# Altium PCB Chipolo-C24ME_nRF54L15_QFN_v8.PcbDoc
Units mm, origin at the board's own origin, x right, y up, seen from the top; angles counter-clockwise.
Board outline 27.05 x 32.39 mm, 2 copper layers (Top Layer, Bottom Layer), stack 0.58 mm thick; 46 components, 34 nets, 183 pads, 310 vias.
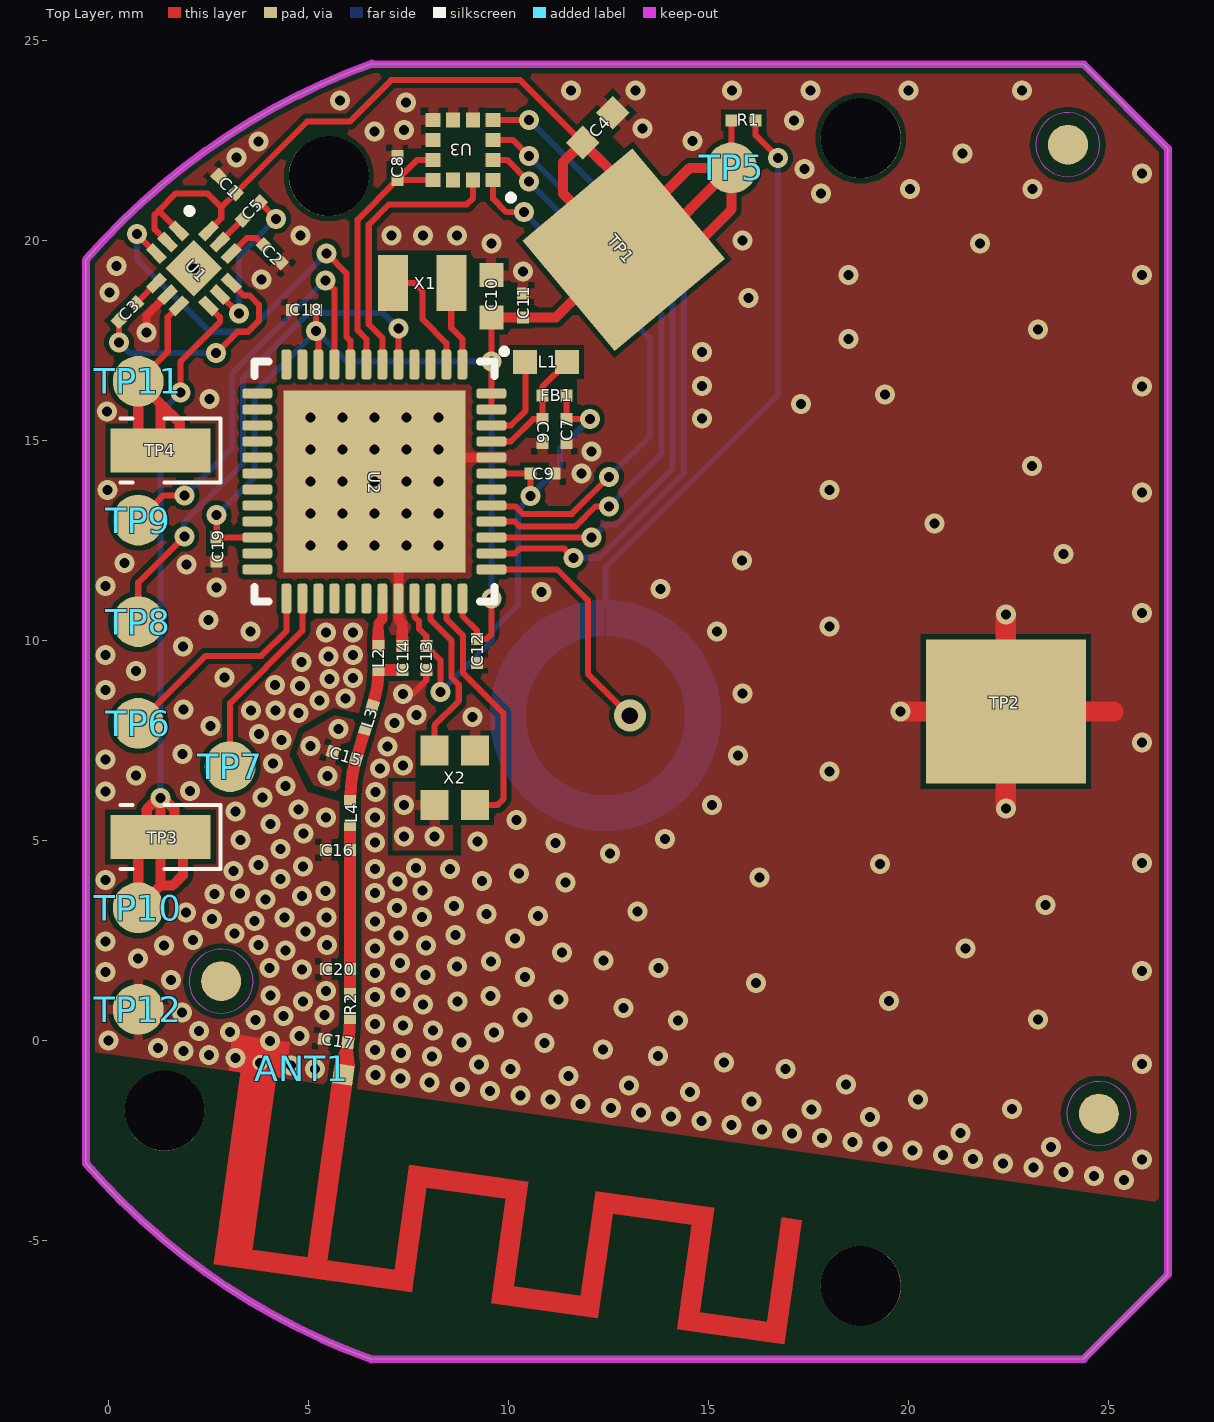
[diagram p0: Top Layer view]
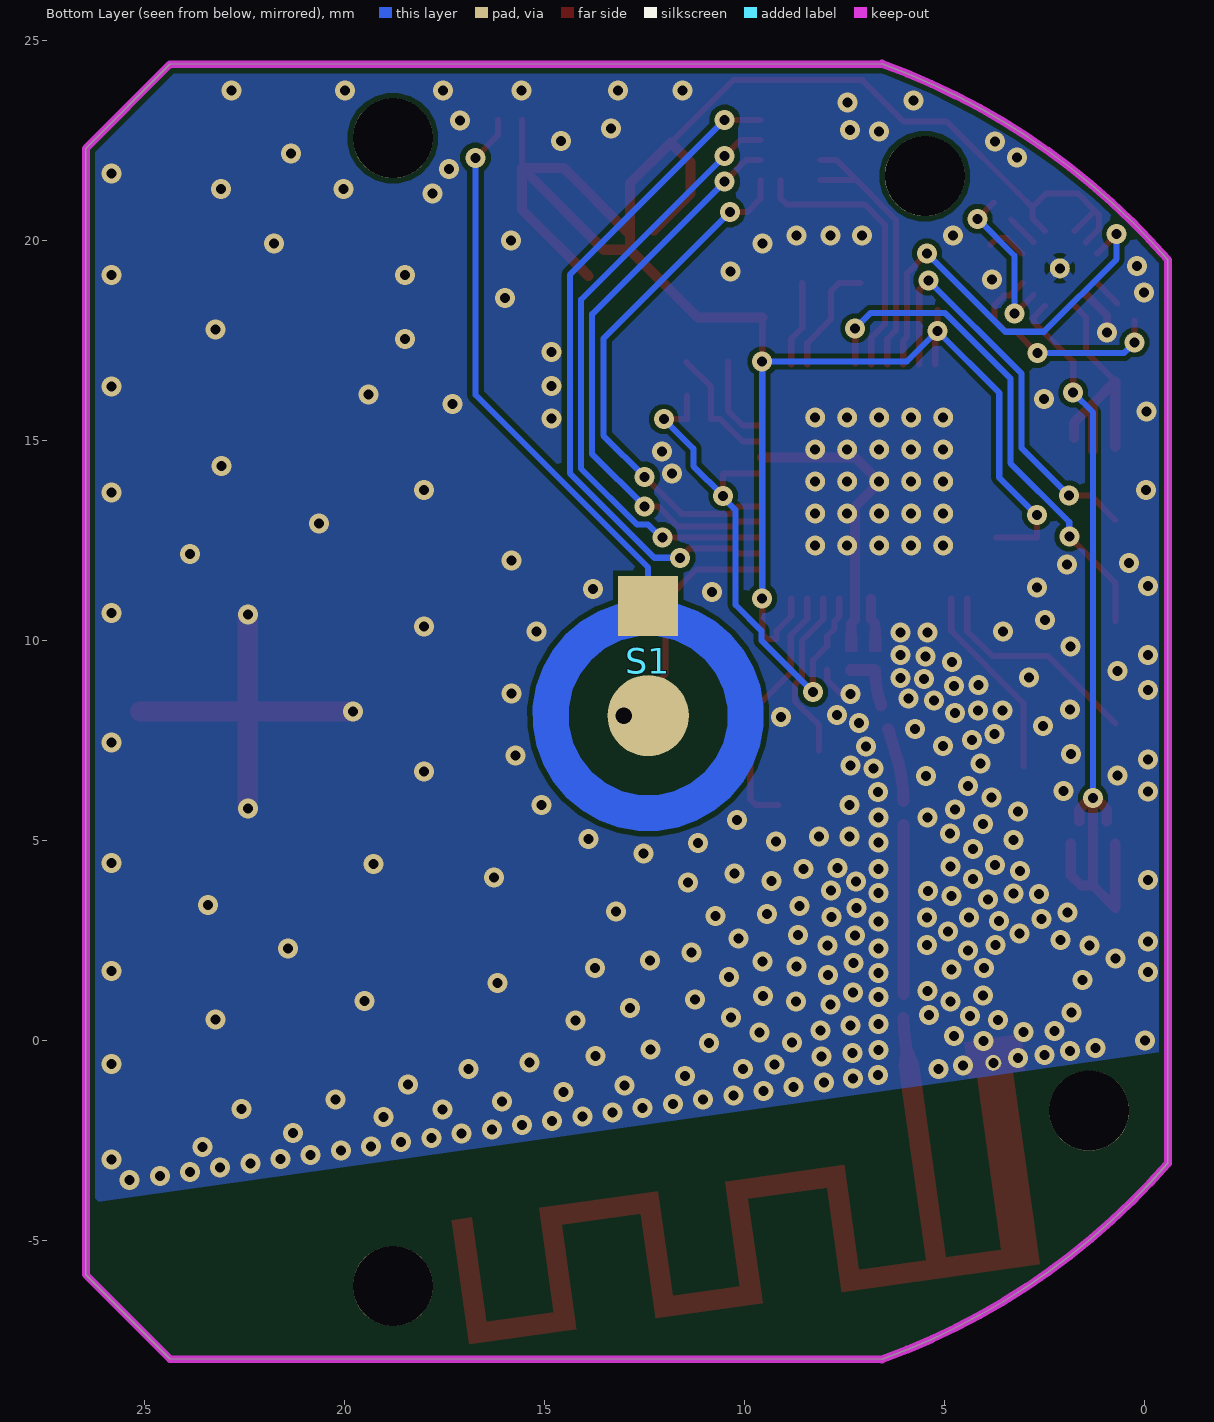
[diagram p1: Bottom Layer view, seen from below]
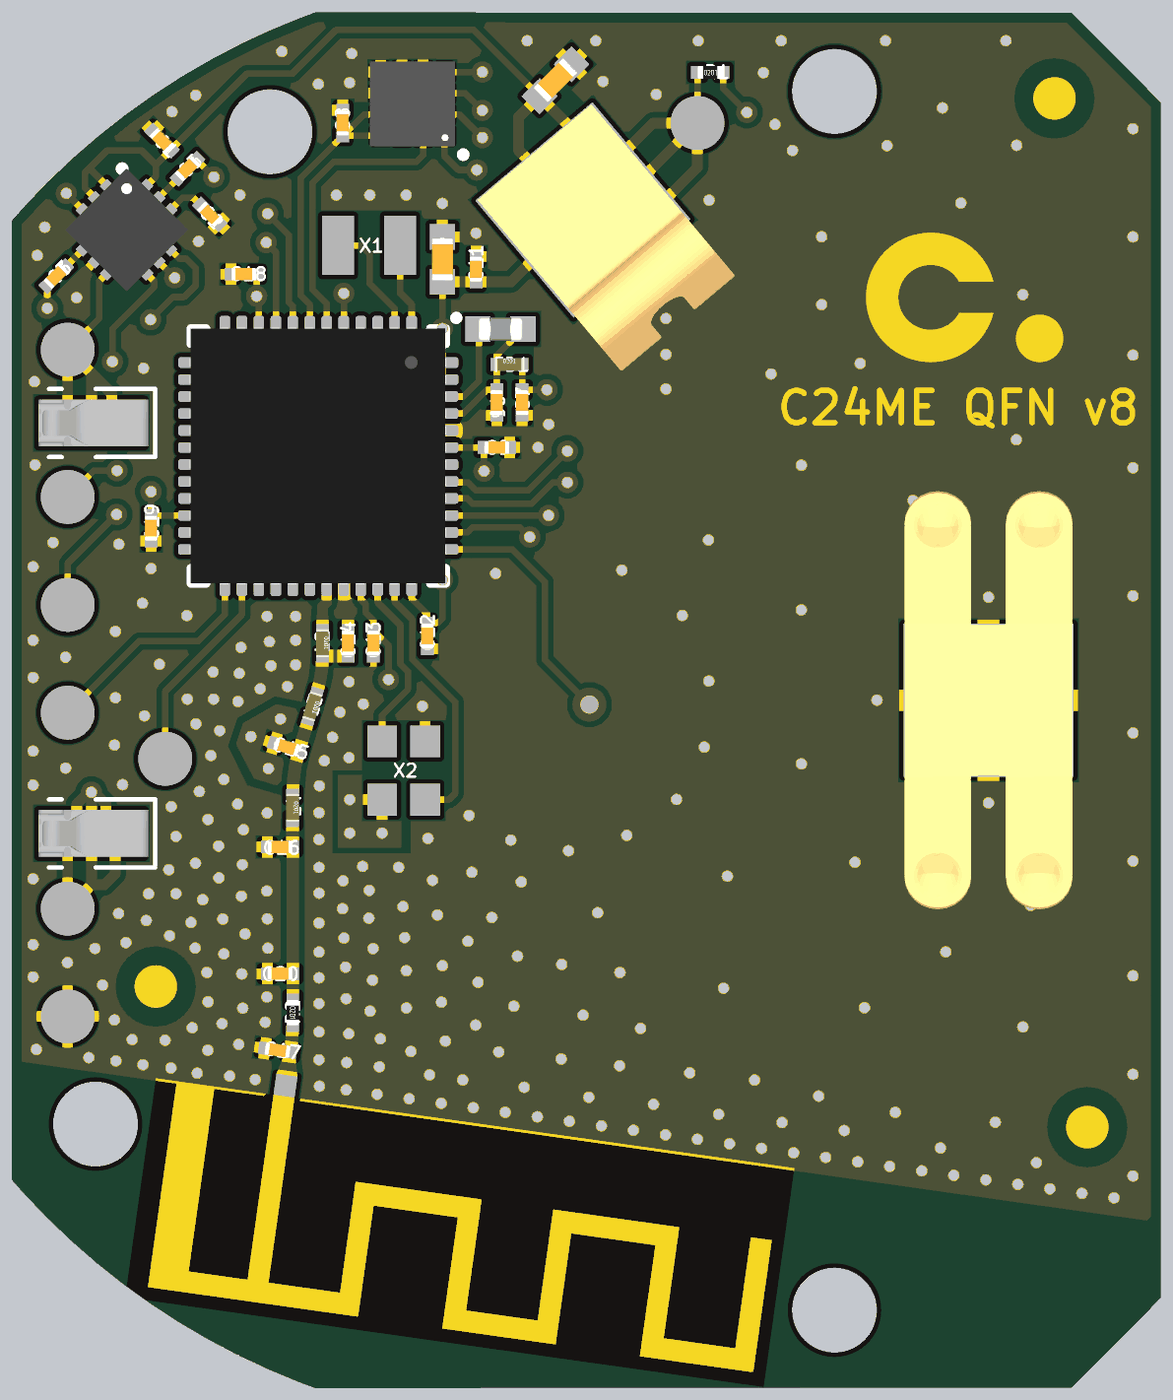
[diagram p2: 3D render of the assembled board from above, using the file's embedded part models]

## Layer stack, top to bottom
Top Solder: solder mask 0.0102, Solder Resist, Dk 3.5
Top Layer: signal copper 0.0356
Dielectric 1: dielectric 0.5086, FR-4, Dk 4.8
Bottom Layer: signal copper 0.0356
Bottom Solder: solder mask 0.0102, Solder Resist, Dk 3.5

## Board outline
-0.574,-3.072 -0.574,19.514 cw(c12.434,8.208) 5.235,23.867 5.233,23.868 cw(c12.426,8.221) 6.573,24.416 24.377,24.403 26.477,22.301 26.477,-5.858 24.377,-7.96 6.573,-7.974 cw(c12.425,8.22)

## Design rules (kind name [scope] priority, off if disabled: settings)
Clearance [All] p1: gap=0.127 ignorepadtopadclearanceinfootprint=FALSE except(0: Arc-Hole Track-Hole SMDPad-Hole THPad-Hole Via-Hole Fill-Hole Poly-Hole Region-Hole Text-Hole)
Clearance Clearance_Polygon [InPolygon] p2: gap=0.127 ignorepadtopadclearanceinfootprint=FALSE
HoleToHoleClearance [All] p1: gap=0.127 allowstackedmicrovias=TRUE
MinimumSolderMaskSliver [All] p1: minsoldermaskwidth=0
PolygonConnect PolygonConnect-ThermalPad [InComponent('U2') AND InNet('GND')] p1: connectstyle=Direct reliefconductorwidth=0.254 reliefentries=4 polygonreliefangle="90 Angle" airgapwidth=0.254
PolygonConnect PolygonConnect_Vias [IsVia] p2: connectstyle=Direct reliefconductorwidth=0.254 reliefentries=4 polygonreliefangle="90 Angle" airgapwidth=0.254
PolygonConnect PolygonConnect_Antenna [(InComponent('ANT1') AND InNet('GND'))] p3: connectstyle=Direct reliefconductorwidth=0.254 reliefentries=4 polygonreliefangle="90 Angle" airgapwidth=0.254
PolygonConnect PolygonConnect_Pads [(InPadClass('All Pads'))] p4: connectstyle=Relief reliefconductorwidth=0.254 reliefentries=4 polygonreliefangle="90 Angle" airgapwidth=0.127
RoutingVias [All] p1: holewidth=0.25 width=0.5 viastyle="Through Hole" minholewidth=0.25 minwidth=0.25 maxholewidth=0.5 maxwidth=1
ShortCircuit ShortCircuit_Antenna [InComponent('ANT1')] p1: allowed=TRUE
ShortCircuit [All] p2: allowed=FALSE
SilkToSilkClearance [All] p1: silktosilkclearance=0.152
SilkToSolderMaskClearance [IsPad] p1: minsilkscreentomaskgap=0.15 clearancetoexposedcopper=TRUE
SolderMaskExpansion SolderMaskExpansion_U1 [InComponent('U1')] p1: expansion=0.048 istentingtop=FALSE
SolderMaskExpansion [All] p2: expansion=0.102 istentingtop=FALSE
Width [All] p1: maxlimit=0.762 minlimit=0.127 preferedwidth=0.152 minimp=50.000000 maximp=50.000000 favimp=50.000000
25 further rules are at their usual default settings.

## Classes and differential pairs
net class C20_Nets: GND NetC16_1
net class FB1_Nets: DECA DECD
net class C9_Nets: DECA GND
net class X1_Nets: NetU2_1 NetU2_2
net class S1_Nets: BTN NetR1_2
net class R2_Nets: NetC16_1 RF
net class C12_Nets: GND Vcc
net class U3_Nets: GND IMU-PWR INT1 SPI-CLK SPI-CS SPI-SDI SPI-SDO Vcc
net class TP11_Nets: BUZ2
net class TP8_Nets: TX
net class C19_Nets: GND Vcc
net class C17_Nets: GND RF
net class C18_Nets: GND VCC
net class C16_Nets: GND NetC16_1
net class C14_Nets: GND NetC14_1
net class C8_Nets: GND IMU-PWR Vcc
net class TP10_Nets: BUZ1
net class TP9_Nets: RX
net class L4_Nets: NetC15_1 NetC16_1
net class C11_Nets: GND Vcc
net class C4_Nets: GND VCC
net class TP7_Nets: SWDCLK
net class TP6_Nets: SWDIO
net class TP12_Nets: GND
net class TP5_Nets: VCC
net class X2_Nets: GND XC1 XC2
net class U1_Nets: BUZ1 BUZ2 GND NetC2_1 NetC3_1 NetC3_2 NetC5_1 NetC5_2 PWM VCC
net class U2_Nets: ANT BTN DECA DECD GND IMU-PWR INT1 NetL1_2 NetU2_1 NetU2_2 PWM RX SPI-CLK SPI-CS SPI-SDI SPI-SDO SWDCLK SWDIO TX VCC XC1 XC2
net class TP4_Nets: BUZ2
net class TP3_Nets: BUZ1
net class TP2_Nets: GND
net class TP1_Nets: VCC
net class R1_Nets: NetR1_2 VCC
net class L3_Nets: NetC14_1 NetC15_1
net class L2_Nets: ANT NetC14_1
net class L1_Nets: DECD NetL1_2
net class ANT1_Nets: GND RF
net class C10_Nets: GND VCC
net class C7_Nets: DECA GND
net class C6_Nets: DECD GND
net class C15_Nets: GND NetC15_1
net class C13_Nets: DECA GND
net class C2_Nets: GND NetC2_1
net class C5_Nets: NetC5_1 NetC5_2
net class C3_Nets: NetC3_1 NetC3_2
net class C1_Nets: GND VCC

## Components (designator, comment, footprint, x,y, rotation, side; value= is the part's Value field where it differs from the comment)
ANT1 "ANTENNA-2.4GHz MIFA" "ANTENNA-2.4GHZ MIFA METABO SHORTENED" 5.871,-0.827 r352 top
C1 "100n" CC0201 2.959,21.398 r315 top
C2 "100n" CC0201 4.085,19.665 r315 top
C3 "100n" CC0201 0.469,18.209 r45 top
C4 "2u2" CC0402 12.226,22.82 r45 top
C5 "100n" CC0201 3.562,20.736 r45 top
C6 "2u2" CC0201 10.842,15.232 r270 top
C7 "2u2" CC0201 11.442,15.232 r270 top
C8 "100n" CC0201 7.216,21.812 r90 top
C9 "10n" CC0201 10.844,14.173 r180 top
C10 "10u" CC0402 9.564,18.602 r90 top
C11 "100n" CC0201 10.356,18.372 r90 top
C12 "100n" CC0201 9.208,9.738 r270 top
C13 "10n" CC0201 7.939,9.564 r270 top
C14 "1.5p" CC0201 7.34,9.564 r90 top
C15 "2.0p" CC0201 5.897,7.118 r163 top
C16 "0.3p" CC0201 5.737,4.766 r180 top
C17 "DNM" CC0201 5.682,-0.017 r172 top
C18 "100n" CC0201 4.887,18.254 r180 top
C19 "100n" CC0201 2.701,12.273 r270 top
C20 "DNM" CC0201 5.738,1.782 r180 top
FB1 "120Ohm, 200mA" LC0201 11.142,16.127 r0 top
L1 "4.7uH" LC0402 10.931,16.96 r180 top
L2 "2.7nH" LC0201 6.74,9.564 r270 top
L3 "3.5nH" LC0201 6.504,8.078 r253 top
L4 "3.5nH" LC0201 6.037,5.689 r270 top
R1 "1k" RC0201 15.872,23.004 r0 top
R2 "0R" RC0201 6.038,0.865 r270 top
S1 "H5C-250-5D-Ni" BTN_DOME_METAL_DOMES_DOUBLE_SIDED_5MM 12.417,8.121 r90 bottom
TP1 "Keystone 122" BATTERY-CONTACT-METABO_POSITIVE 12.873,19.766 r310 top
TP2 "Keystone 112" BATTERY-CONTACT-METABO_NEGATIVE 22.426,8.222 r90 top
TP3 "AMPHENOL 10123973-014RLF" "AMPHENOL 10123973-014RLF" 1.296,5.086 r0 top
TP4 "AMPHENOL 10123973-014RLF" "AMPHENOL 10123973-014RLF" 1.296,14.75 r0 top locked
TP5 "" PIN-1.27X1.27-E-TH 15.572,21.812 r90 bottom
TP6 "" PIN-1.27X1.27-E-TH 0.738,7.928 r90 bottom
TP7 "" PIN-1.27X1.27-E-TH 3.035,6.843 r90 bottom
TP8 "" PIN-1.27X1.27-E-TH 0.738,10.468 r0 bottom
TP9 "" PIN-1.27X1.27-E-TH 0.738,13.008 r0 bottom
TP10 "" PIN-1.27X1.27-E-TH 0.738,3.316 r90 bottom
TP11 "" PIN-1.27X1.27-E-TH 0.738,16.476 r90 bottom
TP12 "" PIN-1.27X1.27-E-TH 0.738,0.776 r90 bottom
U1 "MAS6240E2" MAS6240-QFN2020-12 2.127,19.301 r315 top value=MAS6240D3
U2 "nRF54L15_QFAA" NRF54L15-QFN48 6.64,13.973 r270 top
U3 "LIS2DH12TR" LIS2DH12TR 8.86,22.262 r180 top
X1 "32.768kHz, 9pF, +/-20ppm" CRYSTAL_SMD_2.0X1.2 8.564,18.932 r180 top
X2 "32MHz, 8pF, +/-15ppm, <100ohm ESR" CRYSTAL_SMD_2.0X1.6 8.143,7.253 r270 top

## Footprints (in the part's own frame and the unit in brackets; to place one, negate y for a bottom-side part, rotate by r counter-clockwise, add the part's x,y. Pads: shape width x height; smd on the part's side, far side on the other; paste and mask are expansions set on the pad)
"AMPHENOL 10123973-014RLF" [mm] "CONTACT-SPRING FINGER"
  rect 2.5x1.1 smd: 1(0,0)
  silkscreen extent -1,-0.8 1.5,0.8, body extent -1.24,-0.55 1.36,0.55, height 1.2
"ANTENNA-2.4GHZ MIFA METABO SHORTENED" [mm] "Meandered Inverted F-Antenna"
  rect 0.5x0.5 smd: 1(0,-0.025)
  round 0.4 hole 0.25 mask+0.102: 2(-2.1,-0.025)
  Top Layer region: -2.55,0.225 -1.65,0.225 -1.65,-4.675 -0.25,-4.675 -0.25,0.225 0.25,0.225 0.25,-4.675 1.95,-4.675 1.95,-2.035 4.95,-2.035 4.95,-4.675 6.65,-4.675 6.65,-2.035 9.65,-2.035 9.65,-4.675 11.35,-4.675 11.35,-2.035 11.85,-2.035 11.85,-5.175 9.15,-5.175 9.15,-2.535 7.15,-2.535 7.15,-5.175 4.45,-5.175 4.45,-2.535 2.45,-2.535 2.45,-5.175 -2.55,-5.175
BATTERY-CONTACT-METABO_NEGATIVE [mm]
  rect 3.6x4 smd: 1(0,0)
  body extent -4.92,-1.98 4.92,1.98, height 1.06
BATTERY-CONTACT-METABO_POSITIVE [mm]
  rect 3.6x3.6 smd: 1(0,0)
  body extent -1.78,-1.75 3.5,1.75, height 5.42
BTN_DOME_METAL_DOMES_DOUBLE_SIDED_5MM [mm]
  rect 1.5x1.5 smd: 1(2.743,0)
  round 2.03 smd: 2(0,0)
  Top Layer region: 2.88,-0.025 2.878,-0.277 2.786,-0.771 2.611,-1.242 2.356,-1.675 2.031,-2.058 1.644,-2.378 1.207,-2.627 0.734,-2.796 0.238,-2.881 -0.264,-2.879 -0.759,-2.79 -1.23,-2.616 -1.665,-2.364 -2.049,-2.04 -2.371,-1.654 -2.622,-1.219 -2.793,-0.746 -2.88,-0.251 -2.88,0.251 -2.793,0.746 -2.622,1.218 -2.371,1.654 -2.049,2.04 -1.665,2.364 -1.23,2.616 -0.759,2.79 -0.264,2.879 0.238,2.881 0.734,2.796 1.207,2.627 1.644,2.378 2.031,2.058 2.356,1.675 2.611,1.242 2.786,0.771 2.878,0.277 2.88,0.025 2.88,0.025 2,0.025 1.985,0.248 1.88,0.682 1.682,1.082 1.401,1.428 1.05,1.702 0.646,1.893 0.211,1.989 -0.236,1.986 -0.67,1.884 -1.071,1.689 -1.419,1.41 -1.696,1.06 -1.889,0.658 -1.987,0.223 -1.987,-0.223 -1.889,-0.658 -1.696,-1.06 -1.419,-1.41 -1.071,-1.689 -0.67,-1.884 -0.236,-1.986 0.211,-1.989 0.646,-1.893 1.05,-1.702 1.401,-1.428 1.682,-1.082 1.88,-0.682 1.985,-0.248 2,-0.025 2,-0.025
  body extent -3.15,-3.14 3.15,3.14, height 0.36
CC0201 [mm] "Chip Capacitor, 2-Leads, Body 0,6x0,3mm, IPC High Density"
  rect 0.3x0.3 smd: 1(-0.3,0) 2(0.3,0)
  body extent -0.3,-0.15 0.3,0.15, height 0.35
CC0402 [mm] "Chip Capacitor, 2-Leads, Body 1,0x0,5mm, IPC Medium Density"
  rect 0.6x0.6 smd: 1(-0.53,0) 2(0.53,0)
  body extent -0.5,-0.25 0.5,0.25, height 0.45
CRYSTAL_SMD_2.0X1.2 [mm]
  rect 0.75x1.4 smd: 1(0,0) 2(1.46,0)
  body extent -0.27,-0.65 1.73,0.65, height 0.6
CRYSTAL_SMD_2.0X1.6 [mm]
  rect 0.75x0.7 smd: 1(0,0) 2(1.372,0) 3(1.372,1.016) 4(0,1.016)
  body extent -0.33,-0.3 1.7,1.32, height 0.65
LC0201 [mm] "Chip Inductor, 2-Leads, Body 0,6x0,3mm, IPC High Density"
  rect 0.3x0.3 smd: 1(-0.3,0) 2(0.3,0)
  body extent -0.33,-0.15 0.33,0.15, height 0.31
LC0402 [mm] "Chip Inductor, 2-Leads, Body 1,0x0,5mm, IPC Medium Density"
  rect 0.6x0.6 smd: 1(-0.53,0) 2(0.53,0)
  body extent -0.52,-0.27 0.53,0.28, height 0.55
LIS2DH12TR [mm] "QFN, 12-Leads, Body 2,00x2,00mm, Pitch 0,50mm, IPC High Density"
  rect 0.375x0.35 smd: 1(-0.75,0.75) 2(-0.75,0.25) 3(-0.75,-0.25) 4(-0.75,-0.75) 7(0.75,-0.75) 8(0.75,-0.25) 9(0.75,0.25) 10(0.75,0.75)
  rect 0.35x0.375 smd: 5(-0.25,-0.75) 6(0.25,-0.75) 11(0.25,0.75) 12(-0.25,0.75)
  silkscreen extent -1.22,1.17 -1.17,1.22, body extent -1,-1 1,1, height 1.01
MAS6240-QFN2020-12 [mm]
  rect 0.5x0.25 smd: 1(-0.925,0.4) 2(-0.925,0) 3(-0.925,-0.4) 7(0.925,-0.4) 8(0.925,0) 9(0.925,0.4)
  rect 0.25x0.5 smd: 4(-0.4,-0.925) 5(0,-0.925) 6(0.4,-0.925) 10(0.4,0.925) 11(0,0.925) 12(-0.4,0.925)
  rect 1x1 smd: 13(0,0)
  round 0.5 hole 0.25 mask-0.2: 13(0,0)
  silkscreen extent -1.12,0.91 -1.07,0.97, body extent -1.03,-1.03 1.03,1.03, height 0.9
NRF54L15-QFN48 [mm]
  rrect50% 0.75x0.25 smd: 1(-2.925,2.2) 2(-2.925,1.8) 3(-2.925,1.4) 4(-2.925,1) 5(-2.925,0.6) 6(-2.925,0.2) 7(-2.925,-0.2) 8(-2.925,-0.6) 9(-2.925,-1) 10(-2.925,-1.4) 11(-2.925,-1.8) 12(-2.925,-2.2) 25(2.925,-2.2) 26(2.925,-1.8) 27(2.925,-1.4) 28(2.925,-1) 29(2.925,-0.6) 30(2.925,-0.2) 31(2.925,0.2) 32(2.925,0.6) 33(2.925,1) 34(2.925,1.4) 35(2.925,1.8) 36(2.925,2.2)
  rrect50% 0.25x0.75 smd: 13(-2.2,-2.925) 14(-1.8,-2.925) 15(-1.4,-2.925) 16(-1,-2.925) 17(-0.6,-2.925) 18(-0.2,-2.925) 19(0.2,-2.925) 20(0.6,-2.925) 21(1,-2.925) 22(1.4,-2.925) 23(1.8,-2.925) 24(2.2,-2.925) 37(2.2,2.925) 38(1.8,2.925) 39(1.4,2.925) 40(1,2.925) 41(0.6,2.925) 42(0.2,2.925) 43(-0.2,2.925) 44(-0.6,2.925) 45(-1,2.925) 46(-1.4,2.925) 47(-1.8,2.925) 48(-2.2,2.925)
  round 0.5 hole 0.25 paste+0 mask+0: 49(-1.6,1.6) 49(-1.6,0.8) 49(-1.6,0) 49(-1.6,-0.8) 49(-1.6,-1.6) 49(-0.8,1.6) 49(-0.8,0.8) 49(-0.8,0) 49(-0.8,-0.8) 49(-0.8,-1.6) 49(0,1.6) 49(0,0.8) 49(0,0) 49(0,-0.8) 49(0,-1.6) 49(0.8,1.6) 49(0.8,0.8) 49(0.8,0) 49(0.8,-0.8) 49(0.8,-1.6) 49(1.6,1.6) 49(1.6,0.8) 49(1.6,0) 49(1.6,-0.8) 49(1.6,-1.6)
  rect 4.55x4.55 smd: 49(0,0)
  silkscreen extent -3.27,-3 3,3.27, body extent -3.02,-3.03 3.02,3.01, height 1
PIN-1.27X1.27-E-TH [mm]
  round 1.27 smd far side: 1(0,0)
RC0201 [mm] "Chip Resistor, 2-Leads, Body 0,6x0,3mm, IPC High Density"
  rect 0.3x0.3 smd: 1(-0.3,0) 2(0.3,0)
  body extent -0.3,-0.15 0.3,0.15, height 0.23

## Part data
ANT1: library part "Header 2", "Header, 2-Pin"
C1 C2 C3 C4 C5 C6 C7 C8 C9 C10 C11 C12 C13 C14 C15 C16 C17 C18 C19 C20: library part Cap, "Capacitor"
FB1: library part Inductor, "Ferrite Bead"
L1: library part Inductor, "MLZ1608M4R7WT000 alternative 0402 size PLEA67BCA4R7M-1PT00"
L2 L3 L4: library part Inductor, "Inductor"
R1 R2: library part Res2, "Resistor"
S1: library part BTN_DOME
TP1 TP2 TP5 TP6 TP7 TP8 TP9 TP10 TP11 TP12: library part "TEST PIN"
TP3 TP4: library part "TEST PIN", "Spring finger contact"
U1: library part MAS6240D3, "Piezo Driver with Multi-Mode Charge Pump"
U2: "Bluetooth @r 5.4, IEEE 802.15.4-2006, 2.4 GHz enabled transceiver"
U3: library part LIS2DH12, "MEMS digital output motion sensor: ultra low-power high performance 3-axis “femto” accelerometer"
X1: library part XTAL_SMD3215_32.768kHz_9pF_General, "XTAL SMD 3215, 32.768kHz, Cl=9pF, Total Tol: ±50ppm"
X2: library part XTAL_SMD2016_32MHz_8pF_General, "XTAL SMD 2025, 32MHz, Cl=10pF, Total Tol: ±20ppm, ESR < 100ohm"

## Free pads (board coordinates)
  round 2 hole 2 unplated: 0(1.393,-1.758) 0(5.502,21.606) 0(18.798,-6.14) 0(18.798,22.556)
  round 1 smd paste-1 mask+0: 1(2.813,1.481) 1(23.98,22.392) 1(24.754,-1.83)

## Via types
v1: diameter 0.5, hole 0.25, Top Layer to Bottom Layer, tented both sides, 309 vias
v2: diameter 0.8, hole 0.41, Top Layer to Bottom Layer, tented both sides, 1 vias

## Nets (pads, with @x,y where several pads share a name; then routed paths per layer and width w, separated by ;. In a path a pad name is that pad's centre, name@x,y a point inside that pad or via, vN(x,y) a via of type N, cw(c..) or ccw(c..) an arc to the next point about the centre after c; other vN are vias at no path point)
ANT: L2.1 U2.31 | length 0.8
  Top Layer w0.25: 6.74,10.303 6.74,10.425 6.84,10.525 U2.31
BTN: S1.2 U2.37 | length 6.1
  Top Layer w0.152: U2.37 11.212,11.773 11.979,11.006 11.979,9.168 v2(13.026,8.121)
BUZ1: TP3.1 TP10.1 U1.7 | length 20.5
  Top Layer w0.152: v1(1.79,16.195) 1.79,16.97 2.778,17.958 2.778,18.084 U1.7
  Top Layer w0.254: TP3.1@0.738,4.923 TP10.1 1.296,3.874 ; TP3.1@0.951,5.469 0.951,5.775 1.229,6.054 v1(1.296,6.054) TP3.1 1.296,3.874 ; v1@1.363,6.054 1.641,5.775 TP3.1@1.641,5.469 ; TP3.1@1.854,4.923 1.854,4.13 1.597,3.874 1.296,3.874
  Bottom Layer w0.152: v1(1.296,6.054) 1.296,15.7 v1(1.79,16.195)
BUZ2: TP4.1 TP11.1 U1.6 | length 7
  Top Layer w0.152: TP11.1 1.475,17.213 1.475,18.084 U1.6
  Top Layer w0.254: TP4.1@0.738,14.832 TP11.1 1.296,15.917 ; TP4.1 1.296,15.917 ; TP4.1@1.775,15.059 1.775,15.439 1.296,15.917
DECA: C7.1 C9.2 C13.1 FB1.2 U2.33 U2.43 | length 13.7
  Top Layer w0.152: U2.33 7.64,10.597 7.757,10.48 7.757,10.292 7.939,10.11 C13.1 8.294,9.51 v1(8.294,8.709) ; U2.43 C9.2 v1(10.544,13.616) ; FB1.2 C7.1 v1(12.026,15.532)
  Bottom Layer w0.152: v1(8.294,8.709) 9.585,10 9.585,10.242 10.229,10.886 10.229,13.253 10.544,13.568 v1(10.544,13.616) 11.285,14.357 11.285,14.791 v1(12.026,15.532)
DECD: C6.1 FB1.1 L1.1 U2.45 | length 3.2
  Top Layer w0.152: U2.45 10.053,14.973 10.612,15.532 C6.1 FB1.1 10.842,16.341 L1.1
GND: ANT1.2 C1.1 C2.2 C4.2 C6.2 C7.2 C8.2 C9.1 C10.2 C11.2 C12.2 C13.2 C14.2 C15.2 C16.2 C17.2 C18.2 C19.2 C20.2 TP2.1 TP12.1 U1.5 U1.13 U2.32 U2.44 U2.49 U3.5 U3.6 U3.7 U3.8 X2.2 X2.4 | length 19.5
  Top Layer w0.152: v1(7.363,8.657) 7.592,8.657 7.939,9.004 C13.2
  Top Layer w0.203: v1(0.947,17.701) 0.947,18.121 U1.5
  Top Layer w0.25: U2.49@6.617,13.973 7.24,13.35 U2.32 7.24,10.525 7.34,10.425 7.34,10.303 ; U2.49@6.64,13.973 7.24,14.573 U2.44
  Top Layer w0.508: v1@19.8,8.221 TP2.1 ; v1(22.426,5.803) TP2.1 ; v1(22.426,10.649) TP2.1 ; 25.118,8.221 TP2.1
  other v1: 25.381,-3.496 24.627,-3.39 23.872,-3.284 23.118,-3.178 22.363,-3.072 25.829,-2.98 21.608,-2.965 20.854,-2.859 20.099,-2.753 23.555,-2.666 19.345,-2.647 18.59,-2.541 17.835,-2.435 17.081,-2.329 21.295,-2.321 16.326,-2.223 15.572,-2.117 14.817,-2.011 14.063,-1.905 19.03,-1.911 13.308,-1.799 17.564,-1.722 22.585,-1.715 12.553,-1.693 11.799,-1.587 16.07,-1.53 11.044,-1.481 20.232,-1.481 10.29,-1.375 14.536,-1.293 9.535,-1.269 8.78,-1.163 13.013,-1.127 18.426,-1.099 8.026,-1.057 7.296,-0.954 11.49,-0.891 6.668,-0.865 5.153,-0.71 10.042,-0.718 16.914,-0.721 4.551,-0.626 9.262,-0.599 25.829,-0.586 15.388,-0.553 3.171,-0.438 8.079,-0.408 13.736,-0.385 2.509,-0.36 7.308,-0.309 1.873,-0.27 6.657,-0.243 12.363,-0.227 1.236,-0.194 8.822,-0.049 10.891,-0.059 0,0 4.037,-0.021 4.767,0.116 9.634,0.197 3.03,0.216 2.255,0.233 8.103,0.249 7.356,0.37 6.657,0.414 3.671,0.509 14.231,0.494 23.235,0.527 10.347,0.573 4.374,0.606 5.392,0.64 1.838,0.694 12.876,0.808 7.859,0.901 4.86,0.969 8.715,0.974 19.505,0.981 11.245,1.017 6.657,1.079 9.541,1.112 4.043,1.122 7.296,1.193 5.429,1.235 16.186,1.44 1.558,1.514 10.402,1.581 7.917,1.629 6.657,1.685 -0.078,1.706 25.829,1.733 4.838,1.777 4.015,1.811 13.745,1.81 8.713,1.853 7.28,1.937 9.563,1.973 12.374,2.003 0.731,2.044 11.332,2.196 4.416,2.249 6.657,2.293 21.421,2.295 1.38,2.378 3.739,2.386 5.452,2.383 7.933,2.373 -0.078,2.468 2.108,2.515 10.162,2.548 7.244,2.623 8.675,2.632 3.139,2.677 4.916,2.718 3.642,2.99 6.657,2.975 2.588,3.035 4.391,3.069 5.441,3.076 7.832,3.089 10.73,3.105 9.447,3.165 1.936,3.199 13.22,3.219 7.211,3.313 8.633,3.364 23.416,3.39 3.917,3.525 4.829,3.607 2.642,3.665 3.288,3.667 6.657,3.68 5.426,3.73 7.841,3.745 11.42,3.944 7.222,3.97 9.332,3.981 -0.078,4.016 4.3,4.039 16.276,4.078 10.257,4.17 3.119,4.232 6.657,4.286 8.532,4.286 7.686,4.308 4.853,4.351 3.747,4.384 19.28,4.407 25.829,4.434 12.534,4.677 4.292,4.789 11.173,4.93 6.657,4.943 9.224,4.967 3.289,5.014 13.906,5.041 7.381,5.094 8.143,5.094 4.876,5.174 4.041,5.414 10.193,5.51 5.437,5.567 6.657,5.573 3.176,5.717 4.741,5.776 7.381,5.881 15.078,5.886 3.839,6.072 -0.078,6.225 6.667,6.206 2.03,6.233 4.416,6.356 0.688,6.625 5.466,6.612 18.018,6.723 6.783,6.795 7.362,6.87 4.108,6.92 -0.078,7.024 15.731,7.118 1.842,7.165 5.05,7.366 6.975,7.348 25.829,7.451 4.317,7.505 3.757,7.665 5.747,7.78 2.545,7.854 7.148,7.94 9.092,8.08 7.7,8.132 4.749,8.191 19.8,8.225 3.556,8.248 4.175,8.248 1.865,8.279 5.272,8.492 5.914,8.545 15.839,8.673 -0.078,8.758 4.777,8.856 4.162,8.887 5.526,9.034 2.898,9.067 6.107,9.055 0.688,9.234 4.819,9.465 5.489,9.6 -0.078,9.633 6.107,9.635 1.861,9.843 5.433,10.197 6.107,10.197 3.543,10.217 15.213,10.218 18.018,10.347 2.497,10.504 25.829,10.68 10.817,11.208 13.79,11.284 2.701,11.323 -0.078,11.364 1.942,11.895 0.391,11.935 15.83,11.994 23.872,12.164 20.65,12.926 25.829,13.695 -0.031,13.765 18.018,13.755 11.816,14.173 23.081,14.356 12.068,14.718 14.828,15.549 -0.046,15.724 17.304,15.904 2.522,16.039 19.403,16.152 25.829,16.348 14.828,16.365 14.828,17.209 18.497,17.537 23.235,17.772 15.998,18.555 0.023,18.696 3.818,19.025 18.497,19.134 25.829,19.132 10.356,19.22 0.199,19.361 9.564,19.919 21.776,19.928 15.845,19.996 4.795,20.117 7.066,20.117 7.853,20.117 8.709,20.117 17.809,21.168 20.036,21.28 23.09,21.288 25.829,21.679 17.398,21.781 3.194,22.078 21.34,22.168 3.751,22.467 14.601,22.488 6.641,22.729 7.377,22.762 13.347,22.792 17.127,22.997 7.427,23.447 5.781,23.497 11.561,23.749 13.175,23.749 15.587,23.749 17.545,23.749 20,23.749 22.837,23.749
IMU-PWR: C8.1 U2.7 U3.9 U3.10 | length 7.1
  Top Layer w0.152: U2.7 6.44,17.535 6.222,17.753 6.222,20.518 C8.1 ; U3.10 C8.1 ; U3.9 7.716,22.012 C8.1
INT1: U2.6 U3.12 | length 7
  Top Layer w0.152: U2.6 6.84,17.563 6.501,17.902 6.501,20.394 7.008,20.901 8.954,20.901 9.11,21.057 U3.12
NetC2_1: C2.1 U1.10 | length 1
  Top Layer w0.152: U1.10 3.448,20.056 3.694,20.056 C2.1@3.863,19.888
NetC3_1: C3.1 U1.9 | length 5.8
  Top Layer w0.152: v1(0.257,17.452) C3.1 ; v1(2.688,17.183) 3.221,17.715 3.478,17.715 3.757,17.994 3.757,18.396 3.532,18.62 3.373,18.62 U1.9
  Bottom Layer w0.152: v1(0.257,17.452) 0.526,17.183 v1(2.688,17.183)
NetC3_2: C3.2 U1.4 | length 0.7
  Top Layer w0.152: C3.2 U1.4
NetC5_1: C5.1 U1.11 | length 0.8
  Top Layer w0.152: U1.11 C5.1
NetC5_2: C5.2 U1.8 | length 4
  Top Layer w0.152: U1.8 v1(3.259,18.169) ; C5.2 v1(4.182,20.541)
  Bottom Layer w0.152: v1(3.259,18.169) 3.259,19.618 v1(4.182,20.541)
NetC14_1: C14.1 L2.2 L3.1 | length 1.5
  Top Layer w0.3: L3.1@6.593,8.372 ccw(c4.045,9.249) L2.2@6.74,9.249 ; L2.2 C14.1
NetC15_1: C15.1 L3.2 L4.1 | length 1.8
  Top Layer w0.3: L4.1 cw(c9.949,5.989) C15.1@6.165,6.982 ; C15.1 L3.2
NetC16_1: C16.1 C20.1 L4.2 R2.1 | length 4.2
  Top Layer w0.3: C16.1 L4.2 ; R2.1 C16.1@6.038,4.766
NetL1_2: L1.2 U2.46 | length 2.2
  Top Layer w0.152: U2.46 10.053,15.373 10.423,15.743 L1.2@10.423,16.96
NetR1_2: R1.2 S1.1 | length 14.2
  Top Layer w0.152: R1.2 16.172,22.625 v1(16.734,22.063)
  Bottom Layer w0.152: S1.1 12.417,11.823 16.734,16.14 v1(16.734,22.063)
NetU2_1: U2.1 X1.1 | length 2.1
  Top Layer w0.152: X1.1 8.564,17.813 8.84,17.538 U2.1
NetU2_2: U2.2 X1.2 | length 2.9
  Top Layer w0.152: X1.2 7.65,18.932 7.848,18.734 7.848,18.027 8.44,17.434 U2.2
PWM: U1.3 U2.8 | length 10.6
  Top Layer w0.152: v1(0.706,20.156) U1.3 ; v1(5.447,19.677) 5.942,19.182 5.942,17.593 6.04,17.495 U2.8
  Bottom Layer w0.152: v1(0.706,20.156) 0.706,19.531 2.522,17.715 3.485,17.715 v1(5.447,19.677)
RF: ANT1.1 C17.1 R2.2 | length 1.4
  Top Layer w0.3: ANT1.1 C17.1 ; C17.1@5.982,-0.064 ccw(c1.376,0.665) R2.2
RX: TP9.1 U2.9 | length 10.4
  Top Layer w0.152: TP9.1 1.358,13.628 v1(1.9,13.628) ; v1(5.414,18.998) 5.64,18.772 U2.9
  Bottom Layer w0.152: v1(1.9,13.628) 3.081,14.809 3.081,16.666 v1(5.414,18.998)
SPI-CLK: U2.41 U3.1 | length 13.1
  Top Layer w0.152: U2.41 9.588,13.35 10.169,13.35 10.356,13.162 11.581,13.162 v1(12.507,14.088) ; U3.1 9.61,21.041 9.944,20.707 v1(10.376,20.707)
  Bottom Layer w0.152: v1(10.376,20.707) 13.537,17.546 13.537,15.118 v1(12.507,14.088)
SPI-CS: U2.40 U3.2 | length 14.4
  Top Layer w0.152: U2.40 10.15,12.973 10.271,12.852 11.673,12.852 12.17,13.35 v1(12.507,13.35) ; U3.2 9.96,22.012 v1(10.503,21.469)
  Bottom Layer w0.152: v1(10.503,21.469) 13.816,18.156 13.816,14.659 v1(12.507,13.35)
SPI-SDI: U2.38 U3.4 | length 17.2
  Top Layer w0.152: U2.38 10.15,12.173 10.271,12.293 11.393,12.293 v1(11.62,12.066) ; U3.4 v1@10.501,23.012
  Bottom Layer w0.152: v1@10.501,23.012 14.375,19.138 14.375,14.181 12.26,12.066 v1(11.62,12.066)
  other v1: 10.503,23.012
SPI-SDO: U2.39 U3.3 | length 15.6
  Top Layer w0.152: U2.39 v1(12.064,12.573) ; U3.3 10.101,22.513 v1(10.503,22.11)
  Bottom Layer w0.152: v1(10.503,22.11) 14.096,18.517 14.096,14.297 12.695,12.896 12.417,12.896 12.093,12.573 v1(12.064,12.573)
SWDCLK: TP7.1 U2.26 | length 5
  Top Layer w0.152: TP7.1 3.035,8.434 4.84,10.239 U2.26
SWDIO: TP6.1 U2.25 | length 5.5
  Top Layer w0.152: TP6.1 2.423,9.613 3.819,9.613 4.44,10.234 U2.25
TX: TP8.1 U2.5 | length 12.8
  Top Layer w0.152: TP8.1 0.738,11.445 v1(1.889,12.596) ; U2.5@7.24,16.925 v1(7.24,17.801)
  Bottom Layer w0.152: v1(1.889,12.596) 1.889,12.961 3.361,14.432 3.361,16.55 4.999,18.189 6.852,18.189 v1(7.24,17.801)
VCC: C1.2 C4.1 C10.1 C11.1 C12.1 C18.1 C19.1 R1.1 TP1.1 TP5.1 U1.1 U1.2 U1.12 U2.10 U2.22 U2.36 U2.47 U2.48 | length 60.7
  Top Layer w0.152: U1.2 1.148,20.28 1.148,20.647 1.247,20.746 ; U1.1 1.247,20.746 ; U1.12 2.813,20.553 2.813,20.827 ; v1(2.701,13.132) C19.1 U2.22 ; C18.1 v1(5.187,17.736) 5.24,17.683 U2.10 ; U2.36 8.84,10.61 9.208,10.242 C12.1 9.448,10.038 9.565,10.154 v1(9.565,11.054) ; U2.47 U2.48 C10.1 ; C4.1 10.287,24.009 7.065,24.009 6.026,22.971 4.957,22.971 C1.2 2.813,20.827 ; TP5.1 R1.1 ; 1.247,20.746 1.669,21.168 2.473,21.168 2.813,20.827
  Top Layer w0.254: C10.1 C11.1 11.179,18.072 TP1.1 ; TP1.1@12.278,20.253 11.354,21.177 11.354,21.948 C4.1 12.873,21.423 TP1.1@12.873,20.157 ; TP1.1@13.916,19.114 15.572,20.769 TP5.1 ; TP1.1 13.525,19.766 TP5.1 ; TP1.1 TP1.1@12.873,20.157 ; TP1.1@12.873,20.157 14.529,21.812 TP5.1
  Bottom Layer w0.152: v1(2.701,13.132) 3.64,14.071 3.64,16.189 v1(5.187,17.736) 5.95,16.973 v1(9.565,16.973) v1(9.565,11.054)
XC1: U2.34 X2.1 | length 4.3
  Top Layer w0.152: U2.34 8.04,10.525 8.573,9.991 8.573,9.072 8.75,8.896 8.75,8.481 8.143,7.874 X2.1
XC2: U2.35 X2.3 | length 6.4
  Top Layer w0.152: U2.35 8.44,10.537 8.853,10.125 8.853,9.192 9.865,8.18 9.865,6.03 9.716,5.881 X2.3
pads on no net: U2.3 U2.4 U2.11 U2.12 U2.13 U2.14 U2.15 U2.16 U2.17 U2.18 U2.19 U2.20 U2.21 U2.23 U2.24 U2.27 U2.28 U2.29 U2.30 U2.42 U3.11

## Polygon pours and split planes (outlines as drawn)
GND on Top Layer "TopGND" (solid, remove dead copper, pour order 0): -0.574,-0.245 -0.574,19.514 cw(c12.434,8.208) 5.235,23.867 5.233,23.868 cw(c12.417,8.242) 6.573,24.416 24.377,24.403 26.477,22.301 26.477,-4.075 -0.349,-0.291 cw(c0.01,2.251) -0.574,-0.248 cw(c-0.572,-0.247)
GND on Bottom Layer "BottomGND" (solid, remove dead copper, pour order 1): -0.574,-0.259 -0.574,19.514 cw(c12.434,8.208) 5.235,23.867 5.233,23.868 cw(c12.415,8.247) 6.573,24.416 24.377,24.403 26.477,22.301 26.477,-4.075

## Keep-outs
Top Layer:
  circle w0.025: c24.752,-1.83 r0.8
  circle w0.025: c23.978,22.392 r0.8
  circle w0.025: c2.811,1.481 r0.8
Keep-Out Layer:
  lines w0.2: 6.573,24.416 24.377,24.403 26.477,22.301 26.477,-5.858 24.377,-7.96 6.573,-7.974 cw(c12.425,8.22) -0.574,-3.072 -0.574,19.514 cw(c12.434,8.208) 6.576,24.417

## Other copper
Top Layer:
  region net RF: 6.15,-0.639 6.107,-0.228 5.81,-0.187 5.655,-0.57 5.62,-0.817 6.115,-0.887
  pour cut-out: 11.719,16.404 11.719,16.533 11.449,16.533 11.449,16.404
  pour cut-out: 11.034,17.387 11.034,16.737 10.828,16.737 10.828,17.387
  pour cut-out: 6.208,8.009 5.649,8.13 4.867,7.684 4.703,7.184 5.126,6.377 5.786,6.177 5.787,5.976 4.965,6.219 4.515,7.136 4.734,7.805 5.62,8.314 6.248,8.184
  pour cut-out: 7.666,6.466 7.103,6.466 7.103,4.753 8.6,4.753 8.6,5.498 8.814,5.498 8.814,4.619 6.974,4.619 6.974,6.567 7.666,6.567
  pour cut-out: 6.378,10.542 6.378,10.598 5.174,10.598 5.174,10.543
  region net GND: 7.19,10.014 7.217,10.35 7.462,10.35 7.49,10.014 7.49,9.714 7.19,9.714
  region net ANT: 6.59,10.014 6.617,10.35 6.862,10.35 6.89,10.014 6.89,9.714 6.59,9.714
  pour cut-out: 8.062,19.759 8.062,18.105 7.606,18.105 7.606,19.759
  pour cut-out: 11.997,23.194 11.733,22.93 12.644,22.018 12.909,22.283
  pour cut-out: 8.308,21.198 7.423,21.198 7.423,21.235 8.308,21.235
  pour cut-out: 2.127,18.379 2.562,17.943 1.802,17.182 1.677,17.307 1.677,17.93
  region net GND: 4.407,-0.962 3.003,-0.764 3.091,0.17 4.52,-0.05
  pour cut-out: 7.493,22.193 7.795,22.193 7.795,22.308 7.493,22.308
  pour cut-out: 10.961,20.501 11.644,21.185 11.644,22.359 11.057,22.946 10.878,22.946 10.878,22.886 10.494,22.502 10.494,21.771 10.647,21.618 10.647,20.786 10.855,20.578
  pour cut-out: 7.666,6.751 7.666,6.383 9.636,6.383 9.636,6.751
  pour cut-out: 5.883,8.864 6.943,8.864
  pour cut-out: 9.295,21.827 9.295,22.698 8.424,22.698 8.424,21.827
  pour cut-out: -95.351,-18.779 -95.351,-18.775 -95.351,-19.633
Bottom Layer:
  pour cut-out: 10.181,22.799 10.181,22.326 10.432,22.489 10.51,22.616

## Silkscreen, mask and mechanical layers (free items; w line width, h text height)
Top Solder:
  region: 23.63,16.183 ccw(c23.63,16.742) 24.189,16.742 ccw(c23.63,16.742) 23.63,17.301 ccw(c23.63,16.742) 23.071,16.742 ccw(c23.63,16.742)
  region: 22.544,17.339 cw(c21.065,17.707) 22.543,18.078 21.731,18.078 21.731,18.077 ccw(c21.065,17.707) 21.732,17.339 21.733,17.339
  text "C24ME QFN v8" at 17.383,14.75 h0.76
Bottom Solder:
  text "CAP.0000013.008" at 22.941,2.775 h0.76
Mechanical 1:
  lines w0.2: -0.574,-0.248 26.482,-4.076
Mechanical 2:
  drawing of 3270 lines, arcs and shapes, not listed
Mechanical 3:
  circle w0.127: c2.046,8.109 r7.5
  circle w0.127: c2.046,8.109 r5.85
Mechanical 13:
  lines w0.2: 13.643,8.221 14.091,8.221 ; 13.877,7.58 13.877,8.835
Mechanical 15:
  lines w0.05: 18.238,-6.14 19.359,-6.14 ; 18.798,-6.701 18.798,-5.58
